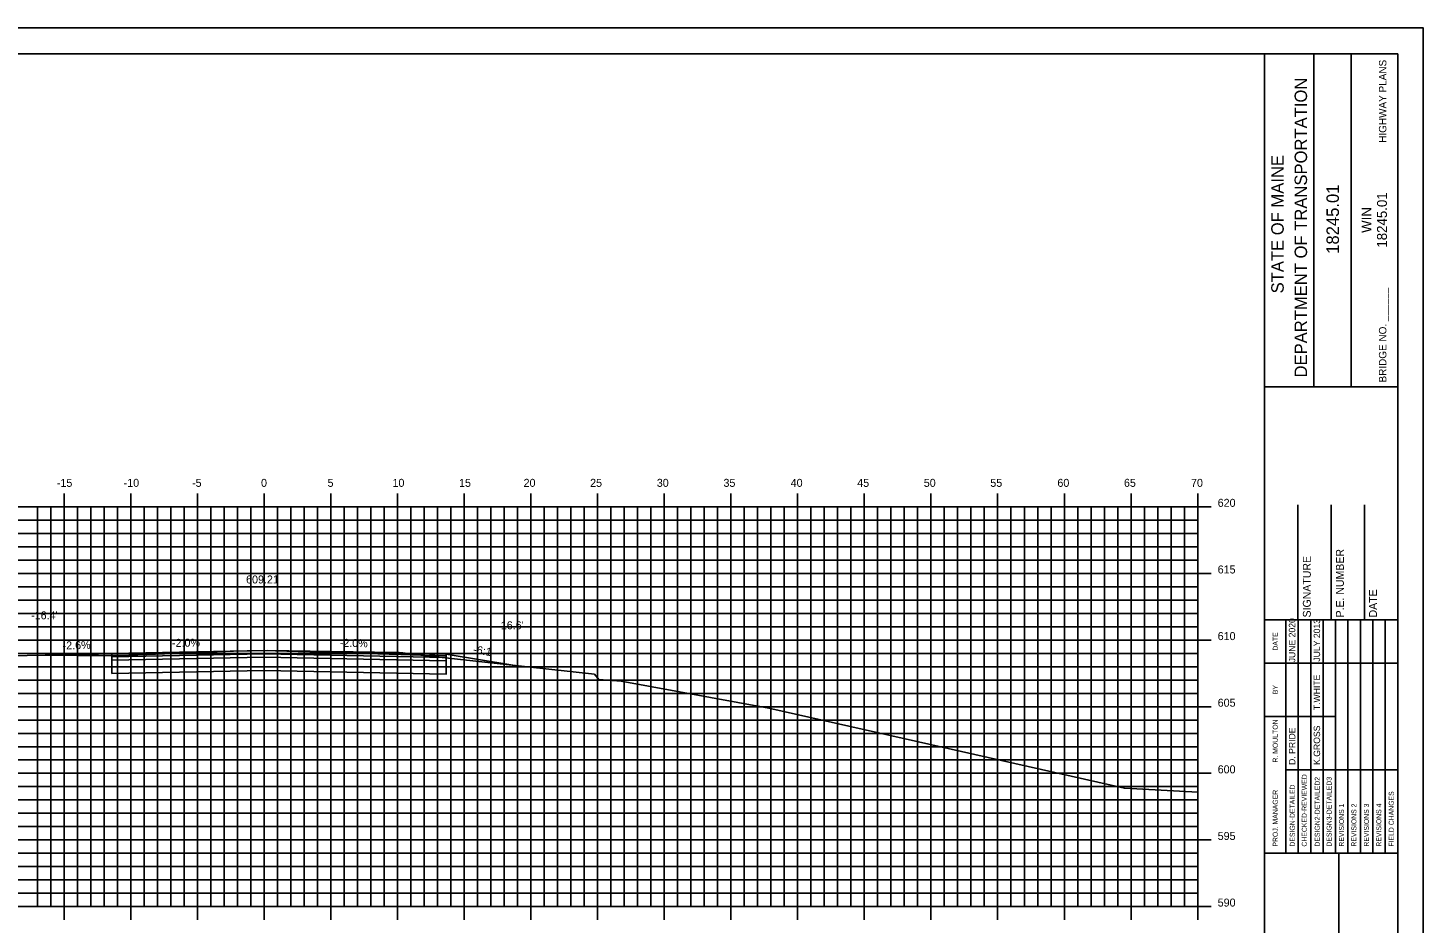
# Model space of a CAD drawing. Extents: x 1048584 to 1048754, y 780904 to 781014.
# Drawn here: x 1048649.5 to 1048754.1, y 780946.9 to 781014.1 of the extents above; entities that cross this region are included whole.
import ezdxf

# ---------------------------------------------------------------- set-up
doc = ezdxf.new("R2010")
doc.units = 0
for name, color, linetype in [('ANNOTATION', 7, 'Continuous'), ('BORDER', 7, 'Continuous'), ('D_Roadway_Centerline', 7, 'Continuous'), ('D_Roadway_Centerline_Text', 7, 'Continuous'), ('D_Roadway_Edge_Pavement', 7, 'Continuous'), ('D_Roadway_Pavement', 7, 'Continuous'), ('D_Roadway_SlopeLines', 7, 'Continuous'), ('D_Roadway_SubGrade', 7, 'Continuous'), ('Default', 7, 'Continuous'), ('H_V ANNOTATION', 7, 'Continuous'), ('MAJOR', 7, 'Continuous'), ('MINOR', 7, 'Continuous'), ('S_Roadway_Centerline', 7, 'Continuous')]:
    doc.layers.add(name, color=color, linetype=linetype)

msp = doc.modelspace()

# ---------------------------------------------------------------- linework, layer by layer
at = {"layer": 'D_Roadway_Centerline'}
msp.add_lwpolyline([(1048650.81, 780966.97), (1048655.81, 780967.1), (1048667.23, 780967.33), (1048680.87, 780967.05), (1048685.87, 780966.22)], dxfattribs=at)
at = {"layer": 'D_Roadway_Edge_Pavement'}
msp.add_lwpolyline([(1048655.81, 780966.85), (1048655.81, 780967.1), (1048667.23, 780967.33), (1048680.87, 780967.05), (1048680.87, 780966.8), (1048667.23, 780967.08)], close=True, dxfattribs=at)
at = {"layer": 'D_Roadway_Pavement'}
msp.add_lwpolyline([(1048655.81, 780966.6), (1048655.81, 780966.85), (1048667.23, 780967.08), (1048680.87, 780966.8), (1048680.87, 780966.55), (1048667.23, 780966.83)], close=True, dxfattribs=at)
at = {"layer": 'D_Roadway_SlopeLines'}
for points in [[(1048655.81, 780967.1), (1048650.81, 780966.97)], [(1048680.87, 780967.05), (1048685.87, 780966.22)]]:
    msp.add_lwpolyline(points, dxfattribs=at)
at = {"layer": 'D_Roadway_SubGrade'}
msp.add_lwpolyline([(1048655.81, 780965.6), (1048655.81, 780966.6), (1048667.23, 780966.83), (1048680.87, 780966.55), (1048680.87, 780965.55), (1048667.23, 780965.83)], close=True, dxfattribs=at)
at = {"layer": 'Default'}
for p, q in [((1048752.23, 781012.11), (1048592.23, 781012.11)), ((1048742.23, 780907.11), (1048742.23, 781012.12)), ((1048745.95, 780987.11), (1048745.95, 781012.11)), ((1048748.75, 780987.11), (1048748.75, 781012.11)), ((1048752.23, 780907.11), (1048752.23, 781012.11)), ((1048742.23, 780987.11), (1048752.23, 780987.11)), ((1048744.73, 780969.62), (1048744.73, 780978.26)), ((1048747.23, 780969.62), (1048747.23, 780978.26)), ((1048749.73, 780969.62), (1048749.73, 780978.26)), ((1048742.23, 780969.62), (1048752.23, 780969.62)), ((1048680.87, 780966.92), (1048667.23, 780967.33)), ((1048742.23, 780952.12), (1048752.23, 780952.12)), ((1048747.82, 780917.12), (1048747.82, 780952.12))]:
    msp.add_line(p, q, dxfattribs=at)
msp.add_lwpolyline([(1048584.13, 780904.06), (1048754.13, 780904.06), (1048754.13, 781014.06), (1048584.13, 781014.06)], close=True, dxfattribs=at)
for points in [[(1048743.84, 780966.37), (1048743.84, 780969.62)], [(1048743.84, 780952.12), (1048743.84, 780968.91)], [(1048744.77, 780952.12), (1048744.77, 780969.62)], [(1048745.71, 780969.62), (1048745.71, 780952.12)], [(1048746.64, 780952.12), (1048746.64, 780969.62)], [(1048747.57, 780952.12), (1048747.57, 780969.62)], [(1048748.5, 780952.12), (1048748.5, 780969.62)], [(1048749.43, 780952.12), (1048749.43, 780969.62)], [(1048750.36, 780952.12), (1048750.36, 780969.62)], [(1048751.3, 780952.12), (1048751.3, 780969.62)], [(1048742.23, 780966.37), (1048752.23, 780966.37)], [(1048742.23, 780962.37), (1048743.84, 780962.37)], [(1048743.84, 780962.37), (1048747.57, 780962.37)], [(1048743.84, 780958.37), (1048752.23, 780958.37)]]:
    msp.add_lwpolyline(points, dxfattribs=at)
at = {"layer": 'MAJOR'}
for p, q in [((1048652.23, 780979.12), (1048652.23, 780978.11)), ((1048657.23, 780979.12), (1048657.23, 780978.11)), ((1048662.23, 780979.12), (1048662.23, 780978.11)), ((1048667.23, 780979.12), (1048667.23, 780978.11)), ((1048672.23, 780979.12), (1048672.23, 780978.11)), ((1048677.23, 780979.12), (1048677.23, 780978.11)), ((1048682.23, 780979.12), (1048682.23, 780978.11)), ((1048687.23, 780979.12), (1048687.23, 780978.11)), ((1048692.23, 780979.12), (1048692.23, 780978.11)), ((1048697.23, 780979.12), (1048697.23, 780978.11)), ((1048702.23, 780979.12), (1048702.23, 780978.11)), ((1048707.23, 780979.12), (1048707.23, 780978.11)), ((1048712.23, 780979.12), (1048712.23, 780978.11)), ((1048717.23, 780979.12), (1048717.23, 780978.11)), ((1048722.23, 780979.12), (1048722.23, 780978.11)), ((1048727.23, 780979.12), (1048727.23, 780978.11)), ((1048732.23, 780979.12), (1048732.23, 780978.11)), ((1048737.23, 780979.12), (1048737.23, 780978.11)), ((1048597.23, 780978.11), (1048737.23, 780978.11)), ((1048597.23, 780978.11), (1048737.23, 780978.11)), ((1048652.23, 780948.11), (1048652.23, 780978.11)), ((1048657.23, 780948.11), (1048657.23, 780978.11)), ((1048662.23, 780948.11), (1048662.23, 780978.11)), ((1048667.23, 780948.11), (1048667.23, 780978.11)), ((1048672.23, 780948.11), (1048672.23, 780978.11)), ((1048677.23, 780948.11), (1048677.23, 780978.11)), ((1048682.23, 780948.11), (1048682.23, 780978.11)), ((1048687.23, 780948.11), (1048687.23, 780978.11)), ((1048692.23, 780948.11), (1048692.23, 780978.11)), ((1048697.23, 780948.11), (1048697.23, 780978.11)), ((1048702.23, 780948.11), (1048702.23, 780978.11)), ((1048707.23, 780948.11), (1048707.23, 780978.11)), ((1048712.23, 780948.11), (1048712.23, 780978.11)), ((1048717.23, 780948.11), (1048717.23, 780978.11)), ((1048722.23, 780948.11), (1048722.23, 780978.11)), ((1048727.23, 780948.11), (1048727.23, 780978.11)), ((1048732.23, 780948.11), (1048732.23, 780978.11)), ((1048738.23, 780978.11), (1048736.22, 780978.11)), ((1048737.23, 780948.11), (1048737.23, 780978.11)), ((1048737.23, 780948.11), (1048737.23, 780978.11)), ((1048597.23, 780973.11), (1048737.23, 780973.11)), ((1048738.23, 780973.11), (1048736.22, 780973.11)), ((1048597.23, 780968.11), (1048737.23, 780968.11)), ((1048738.23, 780968.11), (1048736.22, 780968.11)), ((1048597.23, 780963.11), (1048737.23, 780963.11)), ((1048738.23, 780963.11), (1048736.22, 780963.11)), ((1048597.23, 780958.11), (1048737.23, 780958.11)), ((1048738.23, 780958.11), (1048736.22, 780958.11)), ((1048597.23, 780953.11), (1048737.23, 780953.11)), ((1048738.23, 780953.11), (1048736.22, 780953.11)), ((1048597.23, 780948.11), (1048737.23, 780948.11)), ((1048597.23, 780948.11), (1048737.23, 780948.11)), ((1048652.23, 780947.11), (1048652.23, 780948.11)), ((1048657.23, 780947.11), (1048657.23, 780948.11)), ((1048662.23, 780947.11), (1048662.23, 780948.11)), ((1048667.23, 780947.11), (1048667.23, 780948.11)), ((1048672.23, 780947.11), (1048672.23, 780948.11)), ((1048677.23, 780947.11), (1048677.23, 780948.11)), ((1048682.23, 780947.11), (1048682.23, 780948.11)), ((1048687.23, 780947.11), (1048687.23, 780948.11)), ((1048692.23, 780947.11), (1048692.23, 780948.11)), ((1048697.23, 780947.11), (1048697.23, 780948.11)), ((1048702.23, 780947.11), (1048702.23, 780948.11)), ((1048707.23, 780947.11), (1048707.23, 780948.11)), ((1048712.23, 780947.11), (1048712.23, 780948.11)), ((1048717.23, 780947.11), (1048717.23, 780948.11)), ((1048722.23, 780947.11), (1048722.23, 780948.11)), ((1048727.23, 780947.11), (1048727.23, 780948.11)), ((1048732.23, 780947.11), (1048732.23, 780948.11)), ((1048738.23, 780948.11), (1048736.22, 780948.11)), ((1048737.23, 780947.11), (1048737.23, 780948.11))]:
    msp.add_line(p, q, dxfattribs=at)
at = {"layer": 'MINOR'}
for p, q in [((1048650.23, 780948.11), (1048650.23, 780978.11)), ((1048651.23, 780948.11), (1048651.23, 780978.11)), ((1048653.23, 780948.11), (1048653.23, 780978.11)), ((1048654.23, 780948.11), (1048654.23, 780978.11)), ((1048655.23, 780948.11), (1048655.23, 780978.11)), ((1048656.23, 780948.11), (1048656.23, 780978.11)), ((1048658.23, 780948.11), (1048658.23, 780978.11)), ((1048659.23, 780948.11), (1048659.23, 780978.11)), ((1048660.23, 780948.11), (1048660.23, 780978.11)), ((1048661.23, 780948.11), (1048661.23, 780978.11)), ((1048663.23, 780948.11), (1048663.23, 780978.11)), ((1048664.23, 780948.11), (1048664.23, 780978.11)), ((1048665.23, 780948.11), (1048665.23, 780978.11)), ((1048666.23, 780948.11), (1048666.23, 780978.11)), ((1048668.23, 780948.11), (1048668.23, 780978.11)), ((1048669.23, 780948.11), (1048669.23, 780978.11)), ((1048670.23, 780948.11), (1048670.23, 780978.11)), ((1048671.23, 780948.11), (1048671.23, 780978.11)), ((1048673.23, 780948.11), (1048673.23, 780978.11)), ((1048674.23, 780948.11), (1048674.23, 780978.11)), ((1048675.23, 780948.11), (1048675.23, 780978.11)), ((1048676.23, 780948.11), (1048676.23, 780978.11)), ((1048678.23, 780948.11), (1048678.23, 780978.11)), ((1048679.23, 780948.11), (1048679.23, 780978.11)), ((1048680.23, 780948.11), (1048680.23, 780978.11)), ((1048681.23, 780948.11), (1048681.23, 780978.11)), ((1048683.23, 780948.11), (1048683.23, 780978.11)), ((1048684.23, 780948.11), (1048684.23, 780978.11)), ((1048685.23, 780948.11), (1048685.23, 780978.11)), ((1048686.23, 780948.11), (1048686.23, 780978.11)), ((1048688.23, 780948.11), (1048688.23, 780978.11)), ((1048689.23, 780948.11), (1048689.23, 780978.11)), ((1048690.23, 780948.11), (1048690.23, 780978.11)), ((1048691.23, 780948.11), (1048691.23, 780978.11)), ((1048693.23, 780948.11), (1048693.23, 780978.11)), ((1048694.23, 780948.11), (1048694.23, 780978.11)), ((1048695.23, 780948.11), (1048695.23, 780978.11)), ((1048696.23, 780948.11), (1048696.23, 780978.11)), ((1048698.23, 780948.11), (1048698.23, 780978.11)), ((1048699.23, 780948.11), (1048699.23, 780978.11)), ((1048700.23, 780948.11), (1048700.23, 780978.11)), ((1048701.23, 780948.11), (1048701.23, 780978.11)), ((1048703.23, 780948.11), (1048703.23, 780978.11)), ((1048704.23, 780948.11), (1048704.23, 780978.11)), ((1048705.23, 780948.11), (1048705.23, 780978.11)), ((1048706.23, 780948.11), (1048706.23, 780978.11)), ((1048708.23, 780948.11), (1048708.23, 780978.11)), ((1048709.23, 780948.11), (1048709.23, 780978.11)), ((1048710.23, 780948.11), (1048710.23, 780978.11)), ((1048711.23, 780948.11), (1048711.23, 780978.11)), ((1048713.23, 780948.11), (1048713.23, 780978.11)), ((1048714.23, 780948.11), (1048714.23, 780978.11)), ((1048715.23, 780948.11), (1048715.23, 780978.11)), ((1048716.23, 780948.11), (1048716.23, 780978.11)), ((1048718.23, 780948.11), (1048718.23, 780978.11)), ((1048719.23, 780948.11), (1048719.23, 780978.11)), ((1048720.23, 780948.11), (1048720.23, 780978.11)), ((1048721.23, 780948.11), (1048721.23, 780978.11)), ((1048723.23, 780948.11), (1048723.23, 780978.11)), ((1048724.23, 780948.11), (1048724.23, 780978.11)), ((1048725.23, 780948.11), (1048725.23, 780978.11)), ((1048726.23, 780948.11), (1048726.23, 780978.11)), ((1048728.23, 780948.11), (1048728.23, 780978.11)), ((1048729.23, 780948.11), (1048729.23, 780978.11)), ((1048730.23, 780948.11), (1048730.23, 780978.11)), ((1048731.23, 780948.11), (1048731.23, 780978.11)), ((1048733.23, 780948.11), (1048733.23, 780978.11)), ((1048734.23, 780948.11), (1048734.23, 780978.11)), ((1048735.23, 780948.11), (1048735.23, 780978.11)), ((1048736.23, 780948.11), (1048736.23, 780978.11)), ((1048597.23, 780977.11), (1048737.23, 780977.11)), ((1048737.23, 780977.11), (1048736.22, 780977.11)), ((1048597.23, 780976.11), (1048737.23, 780976.11)), ((1048737.23, 780976.11), (1048736.22, 780976.11)), ((1048597.23, 780975.11), (1048737.23, 780975.11)), ((1048597.23, 780974.11), (1048737.23, 780974.11)), ((1048737.23, 780975.11), (1048736.22, 780975.11)), ((1048737.23, 780974.11), (1048736.22, 780974.11)), ((1048597.23, 780972.11), (1048737.23, 780972.11)), ((1048737.23, 780972.11), (1048736.22, 780972.11)), ((1048597.23, 780971.11), (1048737.23, 780971.11)), ((1048737.23, 780971.11), (1048736.22, 780971.11)), ((1048597.23, 780970.11), (1048737.23, 780970.11)), ((1048737.23, 780970.11), (1048736.22, 780970.11)), ((1048597.23, 780969.11), (1048737.23, 780969.11)), ((1048737.23, 780969.11), (1048736.22, 780969.11)), ((1048597.23, 780967.11), (1048737.23, 780967.11)), ((1048737.23, 780967.11), (1048736.22, 780967.11)), ((1048597.23, 780966.11), (1048737.23, 780966.11)), ((1048737.23, 780966.11), (1048736.22, 780966.11)), ((1048597.23, 780965.11), (1048737.23, 780965.11)), ((1048737.23, 780965.11), (1048736.22, 780965.11)), ((1048597.23, 780964.11), (1048737.23, 780964.11)), ((1048737.23, 780964.11), (1048736.22, 780964.11)), ((1048597.23, 780962.11), (1048737.23, 780962.11)), ((1048737.23, 780962.11), (1048736.22, 780962.11)), ((1048597.23, 780961.11), (1048737.23, 780961.11)), ((1048737.23, 780961.11), (1048736.22, 780961.11)), ((1048597.23, 780960.11), (1048737.23, 780960.11)), ((1048737.23, 780960.11), (1048736.22, 780960.11)), ((1048597.23, 780959.11), (1048737.23, 780959.11)), ((1048737.23, 780959.11), (1048736.22, 780959.11)), ((1048597.23, 780957.11), (1048737.23, 780957.11)), ((1048737.23, 780957.11), (1048736.22, 780957.11)), ((1048597.23, 780956.11), (1048737.23, 780956.11)), ((1048737.23, 780956.11), (1048736.22, 780956.11)), ((1048597.23, 780955.11), (1048737.23, 780955.11)), ((1048737.23, 780955.11), (1048736.22, 780955.11)), ((1048597.23, 780954.11), (1048737.23, 780954.11)), ((1048737.23, 780954.11), (1048736.22, 780954.11)), ((1048597.23, 780952.11), (1048737.23, 780952.11)), ((1048597.23, 780951.11), (1048737.23, 780951.11)), ((1048737.23, 780952.11), (1048736.22, 780952.11)), ((1048737.23, 780951.11), (1048736.22, 780951.11)), ((1048597.23, 780950.11), (1048737.23, 780950.11)), ((1048737.23, 780950.11), (1048736.22, 780950.11)), ((1048597.23, 780949.11), (1048737.23, 780949.11)), ((1048737.23, 780949.11), (1048736.22, 780949.11))]:
    msp.add_line(p, q, dxfattribs=at)
at = {"layer": 'S_Roadway_Centerline'}
msp.add_lwpolyline([(1048646.3, 780966.89), (1048651.04, 780966.97), (1048653.23, 780966.94), (1048655.41, 780966.95), (1048656.41, 780966.96), (1048663.11, 780967.21), (1048664.92, 780967.27), (1048667.47, 780967.33), (1048677.11, 780967.17), (1048677.34, 780967.17), (1048677.63, 780967.16), (1048678.3, 780967.06), (1048691.99, 780965.54), (1048692.33, 780965.16), (1048694, 780965.03), (1048705.06, 780963), (1048731.74, 780956.99), (1048737.23, 780956.69)], dxfattribs=at)

# ---------------------------------------------------------------- texts
at = {"layer": 'ANNOTATION'}
for s, rotation, p in [("-16.4'", 360, (1048649.75, 780969.67)), ("16.6'", 360, (1048684.97, 780968.92)), ('-2.6%', 1.5035, (1048652.12, 780967.4)), ('-2.0%', 1.1458, (1048660.32, 780967.59)), ('-2.0%', 358.8542, (1048672.89, 780967.61)), ('-6:1', 350.546, (1048682.87, 780967.13))]:
    msp.add_text(s, height=0.6, rotation=rotation, dxfattribs=at).set_placement(p)
at = {"layer": 'BORDER'}
for s, p in [('DEPARTMENT OF TRANSPORTATION', (1048745.43, 780987.82)), ('STATE OF MAINE', (1048743.68, 780994.13))]:
    msp.add_text(s, height=0.9318, rotation=90, dxfattribs=at).set_placement(p)
at = {"layer": 'D_Roadway_Centerline_Text'}
msp.add_text('609.21', height=0.6, dxfattribs=at).set_placement((1048665.87, 780972.36))
at = {"layer": 'Default'}
for s, height, p in [('HIGHWAY PLANS', 0.559, (1048751.38, 781005.43)), ('18245.01', 0.932, (1048747.82, 780997.1)), ('18245.01', 0.745, (1048751.42, 780997.56)), ('WIN', 0.745, (1048750.26, 780998.67)), ('BRIDGE NO. ______', 0.559, (1048751.38, 780987.44)), ('SIGNATURE', 0.591, (1048745.71, 780969.81)), ('P.E. NUMBER', 0.5906, (1048748.19, 780969.81)), ('DATE', 0.591, (1048750.67, 780969.81)), ('JUNE 2020', 0.485, (1048744.55, 780966.44)), ('JULY 2013', 0.485, (1048746.41, 780966.49)), ('DATE', 0.371, (1048743.23, 780967.32)), ('BY', 0.371, (1048743.23, 780964.05)), ('T.WHITE', 0.485, (1048746.41, 780962.85)), ('R. MOULTON', 0.373, (1048743.23, 780958.92)), ('K.GROSS', 0.485, (1048746.41, 780958.74)), ('D. PRIDE', 0.485, (1048744.55, 780958.74)), ('CHECKED-REVIEWED', 0.3727, (1048745.41, 780952.61)), ('DESIGN2-DETAILED2', 0.3727, (1048746.38, 780952.61)), ('DESIGN3-DETAILED3', 0.3727, (1048747.27, 780952.61)), ('PROJ. MANAGER', 0.3727, (1048743.23, 780952.61)), ('DESIGN-DETAILED', 0.3727, (1048744.51, 780952.61)), ('FIELD CHANGES', 0.3727, (1048751.93, 780952.61)), ('REVISIONS 1', 0.3727, (1048748.2, 780952.61)), ('REVISIONS 2', 0.3727, (1048749.13, 780952.61)), ('REVISIONS 3', 0.3727, (1048750.07, 780952.61)), ('REVISIONS 4', 0.3727, (1048751, 780952.61))]:
    msp.add_text(s, height=height, rotation=90, dxfattribs=at).set_placement(p)
at = {"layer": 'H_V ANNOTATION'}
for s, p in [('-15', (1048651.68, 780979.61)), ('-10', (1048656.69, 780979.61)), ('-5', (1048661.82, 780979.61)), ('0', (1048666.99, 780979.61)), ('5', (1048671.98, 780979.61)), ('10', (1048676.85, 780979.61)), ('15', (1048681.84, 780979.61)), ('20', (1048686.68, 780979.61)), ('25', (1048691.67, 780979.61)), ('30', (1048696.67, 780979.61)), ('35', (1048701.67, 780979.61)), ('40', (1048706.71, 780979.61)), ('45', (1048711.7, 780979.61)), ('50', (1048716.69, 780979.61)), ('55', (1048721.68, 780979.61)), ('60', (1048726.71, 780979.61)), ('65', (1048731.7, 780979.61)), ('70', (1048736.73, 780979.61)), ('620', (1048738.73, 780978.11)), ('615', (1048738.73, 780973.11)), ('610', (1048738.73, 780968.11)), ('605', (1048738.73, 780963.11)), ('600', (1048738.73, 780958.11)), ('595', (1048738.73, 780953.11)), ('590', (1048738.73, 780948.11))]:
    msp.add_text(s, height=0.6, dxfattribs=at).set_placement(p)
at = {"layer": 'S_Roadway_Centerline'}
for s, p in [('C', (1048667.46, 780967.33)), ('L', (1048667.47, 780967.33))]:
    msp.add_text(s, height=0.0146, dxfattribs=at).set_placement(p)

doc.saveas('drawing.dxf')
